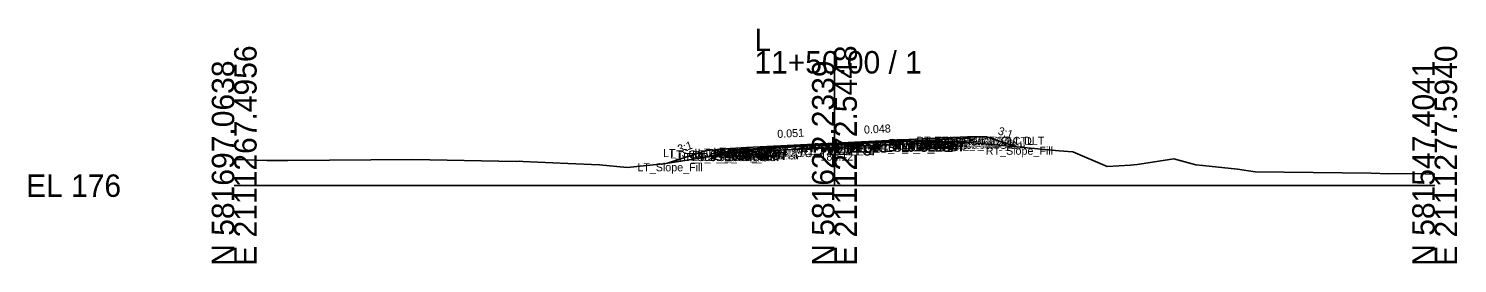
# Model space of a CAD drawing. Extents: x -26 to 3453, y -333 to 9539.
# Drawn here: x -25.7 to 152.8, y 990.3 to 1019.6 of the extents above; entities that cross this region are included whole.
import ezdxf

# ---------------------------------------------------------------- set-up
doc = ezdxf.new("R2010")
doc.units = 0
for name, color, linetype in [('Default', 7, 'Continuous'), ('Exist Cross Section Cell', 7, 'Continuous'), ('Exist XS Center Line Elevation Label', 7, 'Continuous'), ('Exist XS Ground Line', 7, 'Continuous'), ('Prop CMT Pvmt Course 1', 7, 'Continuous'), ('Prop CMT Pvmt Course 1 Wedge', 7, 'Continuous'), ('Prop CMT Pvmt Course 2', 7, 'Continuous'), ('Prop CMT Pvmt Course 2 Wedge', 7, 'Continuous'), ('Prop CMT Pvmt Course 3', 7, 'Continuous'), ('Prop CMT Pvmt Surface', 7, 'Continuous'), ('Prop CMT Pvmt Surface Shoulder', 7, 'Continuous'), ('Prop CMT Pvmt Wedge Surface 1', 7, 'Continuous'), ('Prop CMT Pvmt Wedge Surface 2', 7, 'Continuous'), ('Prop CMT Pvmt Wedge Surface 3', 7, 'Continuous'), ('Prop CMT Shld Paved Course 1', 7, 'Continuous'), ('Prop CMT Shld Paved Course 2', 7, 'Continuous'), ('Prop CMT Shld Paved Course 3', 7, 'Continuous'), ('Prop CMT Slope Grass', 7, 'Continuous'), ('Prop CMT Subgrade Earthwork', 7, 'Continuous'), ('Prop XS SE Text', 7, 'Continuous'), ('Prop XS Side Slope Text', 7, 'Continuous'), ('Scratch_Level_0', 7, 'Continuous')]:
    doc.layers.add(name, color=color, linetype=linetype)

msp = doc.modelspace()

# ---------------------------------------------------------------- linework, layer by layer
at = {"layer": 'Exist Cross Section Cell'}
for p, q in [((75, 1000), (75, 1016.78)), ((0, 1000), (75, 1000)), ((75, 1000), (150, 1000))]:
    msp.add_line(p, q, dxfattribs=at)
at = {"layer": 'Exist XS Ground Line'}
for p, q in [((75.08, 1005.12), (84.58, 1005.5)), ((84.58, 1005.5), (86.42, 1005.59)), ((86.42, 1005.59), (92.44, 1005.34)), ((92.44, 1005.34), (103.08, 1004.35)), ((53.94, 1002.76), (61.08, 1003.9)), ((61.08, 1003.9), (65.38, 1004.56)), ((65.38, 1004.56), (73.76, 1005.06)), ((73.76, 1005.06), (74.39, 1005.1)), ((74.39, 1005.1), (75.08, 1005.12)), ((103.08, 1004.35), (104.77, 1004.21)), ((104.77, 1004.21), (109.06, 1002.37)), ((113.13, 1002.67), (117.41, 1003.35)), ((117.41, 1003.35), (120.15, 1002.6)), ((0, 1003.24), (4.07, 1003.14)), ((4.07, 1003.14), (6.72, 1003.13)), ((6.72, 1003.13), (22.26, 1003.27)), ((22.26, 1003.27), (35.23, 1003.01)), ((35.23, 1003.01), (35.61, 1003.06)), ((35.61, 1003.06), (36.05, 1003)), ((36.05, 1003), (41.67, 1002.75)), ((41.67, 1002.75), (45.63, 1002.58)), ((45.63, 1002.58), (49.12, 1002.27)), ((49.12, 1002.27), (53.2, 1002.66)), ((53.2, 1002.66), (53.94, 1002.76)), ((109.06, 1002.37), (112.01, 1002.56)), ((112.01, 1002.56), (112.81, 1002.62)), ((112.81, 1002.62), (113.13, 1002.67)), ((120.15, 1002.6), (121.02, 1002.5)), ((121.02, 1002.5), (125.36, 1002.05)), ((125.36, 1002.05), (127.56, 1001.73)), ((127.56, 1001.73), (142.07, 1001.55)), ((142.07, 1001.55), (144.29, 1001.49)), ((144.29, 1001.49), (147.53, 1001.5)), ((147.53, 1001.5), (150, 1001.43))]:
    msp.add_line(p, q, dxfattribs=at)
at = {"layer": 'Prop CMT Pvmt Course 1'}
for points in [[(75, 1005.3), (64, 1004.74)], [(65.39, 1004.68), (75, 1005.18)], [(75, 1005.3), (86, 1005.83)], [(84.59, 1005.64), (75, 1005.18)], [(75, 1005.09), (75, 1005.3)], [(75, 1005.09), (75, 1005.3)], [(75, 1005.18), (75, 1005.09), (75, 1005.09)], [(75, 1005.18), (75, 1005.09), (75, 1005.09)], [(84.59, 1005.56), (84.59, 1005.64)], [(86, 1005.62), (84.59, 1005.56)], [(86, 1005.83), (86, 1005.62)], [(64, 1004.74), (64, 1004.53)], [(64, 1004.53), (65.39, 1004.6)], [(65.39, 1004.6), (65.39, 1004.68)]]:
    msp.add_lwpolyline(points, dxfattribs=at)
at = {"layer": 'Prop CMT Pvmt Course 1 Wedge'}
for points in [[(65.39, 1004.68), (73.76, 1005.11), (74.39, 1005.14), (75, 1005.18)], [(75, 1005.18), (75.08, 1005.18), (84.58, 1005.64), (84.59, 1005.64)], [(84.59, 1005.51), (84.58, 1005.51), (83.26, 1005.45), (75.08, 1005.12), (75, 1005.12)], [(75, 1005.18), (75, 1005.12)], [(75, 1005.12), (75, 1005.18)], [(84.59, 1005.64), (84.59, 1005.51)], [(75, 1005.12), (74.39, 1005.1), (73.76, 1005.06), (65.39, 1004.56)], [(65.39, 1004.56), (65.39, 1004.68)]]:
    msp.add_lwpolyline(points, dxfattribs=at)
at = {"layer": 'Prop CMT Pvmt Course 2'}
for points in [[(84.59, 1005.56), (86, 1005.62)], [(84.59, 1005.22), (84.59, 1005.56)], [(86, 1005.29), (84.59, 1005.22)], [(86, 1005.62), (86, 1005.29)], [(65.39, 1004.6), (64, 1004.53)], [(64, 1004.53), (64, 1004.2)], [(64, 1004.2), (65.39, 1004.27)], [(65.39, 1004.27), (65.39, 1004.6)]]:
    msp.add_lwpolyline(points, dxfattribs=at)
at = {"layer": 'Prop CMT Pvmt Course 2 Wedge'}
for points in [[(78.23, 1005.25), (84.58, 1005.56)], [(84.59, 1005.5), (84.58, 1005.5), (78.23, 1005.25)], [(84.58, 1005.56), (84.59, 1005.56)], [(84.59, 1005.56), (84.59, 1005.5)], [(65.39, 1004.6), (70.19, 1004.85)], [(70.19, 1004.85), (65.39, 1004.56)], [(65.39, 1004.56), (65.39, 1004.6)]]:
    msp.add_lwpolyline(points, dxfattribs=at)
at = {"layer": 'Prop CMT Pvmt Course 3'}
for points in [[(84.59, 1005.22), (86, 1005.29)], [(86, 1005.29), (84.59, 1005.22)], [(84.59, 1005.22), (84.59, 1005.22)], [(86, 1005.29), (86, 1005.29)], [(65.39, 1004.27), (64, 1004.2)], [(64, 1004.2), (65.39, 1004.27)], [(64, 1004.2), (64, 1004.2)], [(65.39, 1004.27), (65.39, 1004.27)]]:
    msp.add_lwpolyline(points, dxfattribs=at)
at = {"layer": 'Prop CMT Pvmt Surface'}
for points in [[(75, 1005.3), (64, 1004.74)], [(75, 1005.3), (86, 1005.83)]]:
    msp.add_lwpolyline(points, dxfattribs=at)
at = {"layer": 'Prop CMT Pvmt Surface Shoulder'}
for points in [[(86, 1005.83), (91.62, 1006.1)], [(64, 1004.74), (62, 1004.63)]]:
    msp.add_lwpolyline(points, dxfattribs=at)
at = {"layer": 'Prop CMT Pvmt Wedge Surface 1'}
for points in [[(75, 1005.18), (65.39, 1004.68)], [(75, 1005.18), (84.59, 1005.64)], [(84.59, 1005.64), (84.59, 1005.56)], [(84.59, 1005.56), (86, 1005.62)], [(86, 1005.62), (86, 1005.83)], [(64, 1004.53), (64, 1004.74)], [(65.39, 1004.6), (64, 1004.53)], [(65.39, 1004.68), (65.39, 1004.6)]]:
    msp.add_lwpolyline(points, dxfattribs=at)
at = {"layer": 'Prop CMT Pvmt Wedge Surface 2'}
for points in [[(75, 1005.09), (86, 1005.62)], [(86, 1005.62), (86, 1005.83)], [(75, 1005.09), (64, 1004.53)], [(64, 1004.53), (64, 1004.74)]]:
    msp.add_lwpolyline(points, dxfattribs=at)
at = {"layer": 'Prop CMT Pvmt Wedge Surface 3'}
for points in [[(75, 1004.76), (86, 1005.29)], [(86, 1005.29), (86, 1005.83)], [(75, 1004.76), (64, 1004.2)], [(64, 1004.2), (64, 1004.74)]]:
    msp.add_lwpolyline(points, dxfattribs=at)
at = {"layer": 'Prop CMT Shld Paved Course 1'}
for points in [[(86, 1005.83), (91.62, 1006.1), (91.82, 1005.91)], [(91.82, 1005.91), (86, 1005.62)], [(86, 1005.62), (86, 1005.83)], [(64, 1004.74), (62, 1004.63), (61.78, 1004.41)], [(61.78, 1004.41), (64, 1004.53)], [(64, 1004.53), (64, 1004.74)]]:
    msp.add_lwpolyline(points, dxfattribs=at)
at = {"layer": 'Prop CMT Shld Paved Course 2'}
for points in [[(86, 1005.62), (91.82, 1005.91), (92.14, 1005.59)], [(86, 1005.29), (86, 1005.62)], [(92.14, 1005.59), (86, 1005.29)], [(64, 1004.53), (61.78, 1004.41), (61.43, 1004.06)], [(61.43, 1004.06), (64, 1004.2)], [(64, 1004.2), (64, 1004.53)]]:
    msp.add_lwpolyline(points, dxfattribs=at)
at = {"layer": 'Prop CMT Shld Paved Course 3'}
for points in [[(86, 1005.29), (92.14, 1005.59)], [(92.14, 1005.59), (86, 1005.29)], [(86, 1005.29), (86, 1005.29)], [(92.14, 1005.59), (92.14, 1005.59), (92.14, 1005.59)], [(64, 1004.2), (61.43, 1004.06)], [(61.43, 1004.06), (64, 1004.2)], [(61.43, 1004.06), (61.43, 1004.06), (61.43, 1004.06)], [(64, 1004.2), (64, 1004.2)]]:
    msp.add_lwpolyline(points, dxfattribs=at)
at = {"layer": 'Prop CMT Slope Grass'}
for points in [[(91.62, 1006.1), (94, 1006.08), (97.73, 1004.85)], [(62, 1004.63), (59, 1004.39), (54.14, 1002.79)]]:
    msp.add_lwpolyline(points, dxfattribs=at)
at = {"layer": 'Prop CMT Subgrade Earthwork'}
for points in [[(84.59, 1005.22), (84.59, 1005.5)], [(84.59, 1005.22), (86, 1005.29)], [(86, 1005.29), (92.14, 1005.59)], [(92.14, 1005.59), (92.65, 1006.09)], [(61.43, 1004.06), (60.94, 1004.55)], [(64, 1004.2), (61.43, 1004.06)], [(65.39, 1004.27), (64, 1004.2)], [(65.39, 1004.27), (65.39, 1004.56)]]:
    msp.add_lwpolyline(points, dxfattribs=at)

# ---------------------------------------------------------------- texts
at = {"layer": 'Default'}
msp.add_text('-', height=0.0001, dxfattribs=at).set_placement((0, 1000))
at = {"layer": 'Exist Cross Section Cell'}
for s, p in [('L', (65, 1016.78)), ('11+50.00 / 1', (65, 1013.98)), ('EL 176', (-26, 998.6))]:
    msp.add_text(s, height=2.8, dxfattribs=at).set_placement(p)
for s, p in [('E 2111267.4956', (2.8, 990)), ('E 2111272.5448', (77.8, 990)), ('E 2111277.5940', (152.8, 990)), ('N 581697.0638', (0, 990)), ('N 581622.2339', (75, 990)), ('N 581547.4041', (150, 990))]:
    msp.add_text(s, height=2.8, rotation=90, dxfattribs=at).set_placement(p)
at = {"layer": 'Exist XS Center Line Elevation Label'}
msp.add_text('181.12', height=1, dxfattribs=at).set_placement((73.25, 1003.12))
at = {"layer": 'Prop XS SE Text'}
for s, rotation, p in [('0.051', 2.931, (67.88, 1005.94)), ('0.048', 2.7698, (78.71, 1006.48))]:
    msp.add_text(s, height=1, rotation=rotation, dxfattribs=at).set_placement(p)
at = {"layer": 'Prop XS Side Slope Text'}
for rotation, p in [(341.7371, (95.35, 1006.42)), (18.2629, (55.58, 1004.06))]:
    msp.add_text('3:1', height=1, rotation=rotation, dxfattribs=at).set_placement(p)
at = {"layer": 'Scratch_Level_0'}
for s, p in [('RT_PV1_IEEOP', (70.83, 1004.18)), ('LT_PV1_IEEOP', (70.89, 1004.18)), ('PV1_PGL', (72.47, 1004.3)), ('RT_PV_OEEOP_EG', (79.13, 1004.5)), ('RT_Sub Tie Out', (79.68, 1004.5)), ('RT_PV2_OEEOP', (79.92, 1004.56)), ('RT_PV3_OEEOP', (79.92, 1004.22)), ('RT_Sub_OEEOP', (79.95, 1004.22)), ('RT_PV1_OEEOP', (80.04, 1004.64)), ('RT_PV2_OEOT', (81.69, 1004.62)), ('RT_PV3_OEOT', (81.69, 1004.29)), ('RT_Sub_OEOT', (81.71, 1004.29)), ('RT_PV1_OEOT', (81.81, 1004.83)), ('RT_Sub_Trench_Out_DLT', (85.24, 1005.09)), ('RT_Sub_Trench_Out', (86.19, 1004.59)), ('RT_PS3_Shelf_Out', (86.74, 1004.59)), ('RT_PS1_OEOP', (87.47, 1005.1)), ('RT_PS2_OEOP', (87.55, 1004.91)), ('RT_PS3_OEOP', (87.87, 1004.59)), ('RT_GS_OS_CTL', (89.4, 1005.08)), ('LT_Sub_Trench_Out_DLT', (53.59, 1003.55)), ('LT_GS_OS_CTL', (54.46, 1003.39)), ('LT_Sub_Trench_Out', (55.54, 1003.06)), ('LT_PS3_Shelf_Out', (56.09, 1003.06)), ('LT_PS3_OEOP', (57.22, 1003.06)), ('LT_PS2_OEOP', (57.57, 1003.41)), ('LT_PS1_OEOP', (57.91, 1003.63)), ('LT_PV2_OEOT', (59.75, 1003.53)), ('LT_PV3_OEOT', (59.75, 1003.2)), ('LT_Sub_OEOT', (59.77, 1003.2)), ('LT_PV1_OEOT', (59.87, 1003.74)), ('LT_PV_OEEOP_EG', (59.99, 1003.56)), ('LT_Sub Tie Out', (60.55, 1003.56)), ('LT_PV2_OEEOP', (60.78, 1003.6)), ('LT_PV3_OEEOP', (60.78, 1003.27)), ('LT_Sub_OEEOP', (60.81, 1003.27)), ('LT_PV1_OEEOP', (60.9, 1003.68)), ('RT_PV_IEEOP_EG', (69.92, 1004.12)), ('LT_PV_IEEOP_EG', (69.98, 1004.12)), ('RT_PV2_IEEOP', (70.71, 1004.09)), ('RT_PV3_IEEOP', (70.71, 1003.76)), ('LT_PV2_IEEOP', (70.77, 1004.09)), ('LT_PV3_IEEOP', (70.77, 1003.76)), ('PV2_PGL', (72.35, 1004.09)), ('RT_Slope_Fill', (93.91, 1003.85)), ('LT_Slope_Fill', (50.37, 1001.79))]:
    msp.add_text(s, height=1, dxfattribs=at).set_placement(p)

doc.saveas('drawing.dxf')
